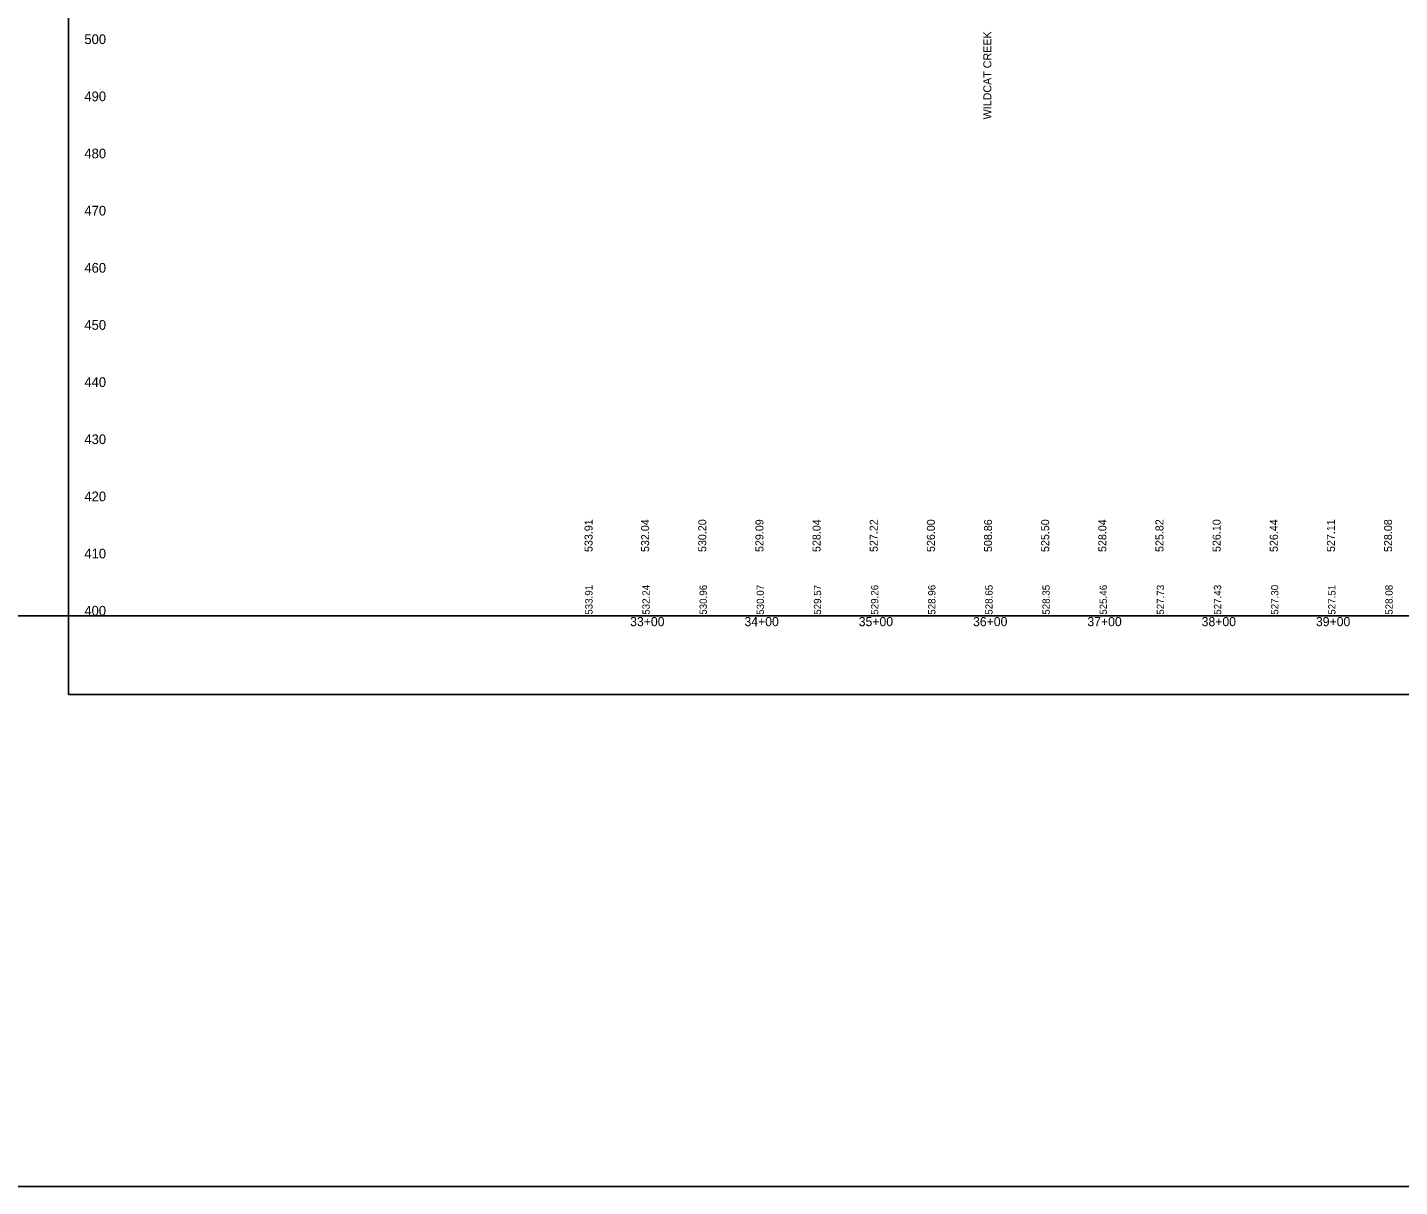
# Model space of a CAD drawing. Extents: x 1979167 to 1986508, y 1111793 to 1113993.
# Drawn here: x 1984194 to 1985395, y 1111793 to 1112807 of the extents above; entities that cross this region are included whole.
import ezdxf

# ---------------------------------------------------------------- set-up
doc = ezdxf.new("R2010")
doc.units = 0
for name, color, linetype in [('RD_DDB_ElevTX', 7, 'Continuous'), ('RD_DDB_Profile_Lbl', 7, 'Continuous'), ('RD_DDB_StaTX', 7, 'Continuous'), ('RD_DDB_StripGrade', 7, 'Continuous'), ('RD_GPK_Profile_Cell', 7, 'Continuous'), ('RD_SHT_IplotShp', 7, 'Continuous'), ('RD_SHT_ShtClip', 7, 'Continuous')]:
    doc.layers.add(name, color=color, linetype=linetype)

msp = doc.modelspace()

# ---------------------------------------------------------------- linework, layer by layer
at = {"layer": 'RD_GPK_Profile_Cell'}
msp.add_line((1983439.2, 1112292), (1985977.7, 1112292), dxfattribs=at)
at = {"layer": 'RD_SHT_IplotShp'}
msp.add_lwpolyline([(1986508.5, 1113992.7), (1982908.5, 1113992.7), (1982908.5, 1111792.7), (1986508.5, 1111792.7)], close=True, dxfattribs=at)
at = {"layer": 'RD_SHT_ShtClip'}
msp.add_lwpolyline([(1984230.3, 1113323.3), (1986030.3, 1113323.3), (1986030.3, 1112223.3), (1984230.3, 1112223.3)], close=True, dxfattribs=at)

# ---------------------------------------------------------------- texts
at = {"layer": 'RD_DDB_ElevTX'}
for s, p in [('500', (1984244.1, 1112792.3)), ('490', (1984244.1, 1112742.3)), ('480', (1984244.1, 1112692.3)), ('470', (1984244.1, 1112642.3)), ('460', (1984244.1, 1112592.3)), ('450', (1984244.1, 1112542.3)), ('440', (1984244.1, 1112492.3)), ('430', (1984244.1, 1112442.3)), ('420', (1984244.1, 1112392.3)), ('410', (1984244.1, 1112342.3)), ('400', (1984244.1, 1112292.3))]:
    msp.add_text(s, height=8.5, dxfattribs=at).set_placement(p)
at = {"layer": 'RD_DDB_Profile_Lbl'}
msp.add_text('WILDCAT CREEK', height=7, rotation=90, dxfattribs=at).set_placement((1985037.6, 1112726.4))
at = {"layer": 'RD_DDB_StaTX'}
for s, p in [('33+00', (1984721.6, 1112283)), ('34+00', (1984821.6, 1112283)), ('35+00', (1984921.6, 1112283)), ('36+00', (1985021.6, 1112283)), ('37+00', (1985121.6, 1112283)), ('38+00', (1985221.6, 1112283)), ('39+00', (1985321.6, 1112283))]:
    msp.add_text(s, height=8, dxfattribs=at).set_placement(p)
at = {"layer": 'RD_DDB_StripGrade'}
for s, height, p in [('533.91', 7, (1984688.7, 1112347.9)), ('532.04', 7, (1984738.2, 1112347.9)), ('530.20', 7, (1984788.2, 1112347.9)), ('529.09', 7, (1984838.2, 1112347.9)), ('528.04', 7, (1984888.2, 1112347.9)), ('527.22', 7, (1984938.2, 1112347.9)), ('526.00', 7, (1984988.2, 1112347.9)), ('508.86', 7, (1985038.2, 1112347.9)), ('525.50', 7, (1985088.2, 1112347.9)), ('528.04', 7, (1985138.2, 1112347.9)), ('525.82', 7, (1985188.2, 1112347.9)), ('526.10', 7, (1985238.2, 1112347.9)), ('526.44', 7, (1985288.2, 1112347.9)), ('527.11', 7, (1985338.2, 1112347.9)), ('528.08', 7, (1985388.2, 1112347.9)), ('533.91', 6.4, (1984688.7, 1112293)), ('532.24', 6.4, (1984738.7, 1112293)), ('530.96', 6.4, (1984788.7, 1112293)), ('530.07', 6.4, (1984838.7, 1112293)), ('529.57', 6.4, (1984888.7, 1112293)), ('529.26', 6.4, (1984938.7, 1112293)), ('528.96', 6.4, (1984988.7, 1112293)), ('528.65', 6.4, (1985038.7, 1112293)), ('528.35', 6.4, (1985088.7, 1112293)), ('525.46', 6.4, (1985138.7, 1112293)), ('527.73', 6.4, (1985188.7, 1112293)), ('527.43', 6.4, (1985238.7, 1112293)), ('527.30', 6.4, (1985288.7, 1112293)), ('527.51', 6.4, (1985338.7, 1112293)), ('528.08', 6.4, (1985388.7, 1112293))]:
    msp.add_text(s, height=height, rotation=90, dxfattribs=at).set_placement(p)

doc.saveas('drawing.dxf')
